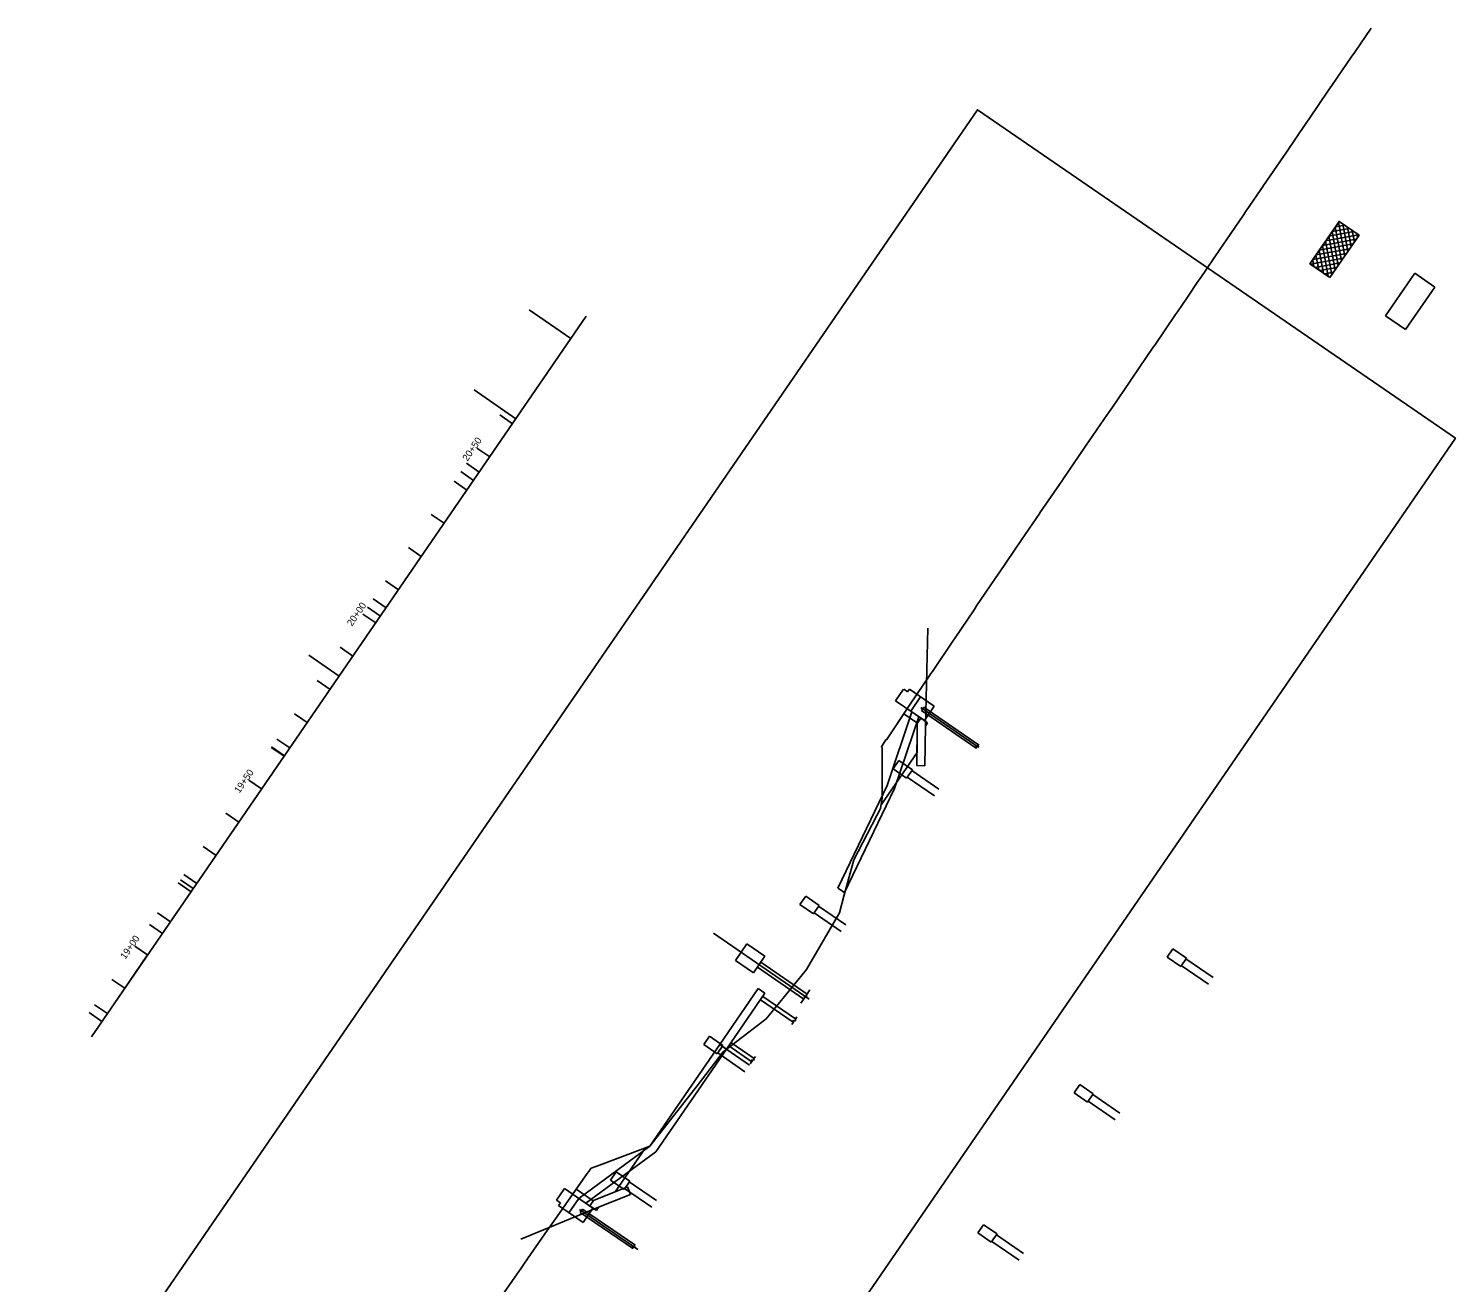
# Model space of a CAD drawing. Extents: x 2379438 to 2380801, y 331550 to 333566.
# Drawn here: x 2379858.6 to 2380212.9, y 332401.2 to 332712.4 of the extents above; entities that cross this region are included whole.
import ezdxf

# ---------------------------------------------------------------- set-up
doc = ezdxf.new("R2010")
doc.units = 0
for name, color, linetype in [('Auto Dimensioning', 7, 'Continuous'), ('Dimension Lines', 7, 'Continuous'), ('Dimension_Lines', 7, 'Continuous'), ('E_SMU_Mis_Existing_Ground_Lines', 7, 'Continuous'), ('E_SMU_Piles_concrete', 7, 'Continuous'), ('Old_Level_10', 7, 'Continuous'), ('P_SMU_Catwalk', 7, 'Continuous'), ('P_SMU_Pipe_Piles', 7, 'Continuous'), ('P_SMU_Steel_Pile', 7, 'Continuous'), ('P_SMU_SupportLines', 7, 'Continuous'), ('P_SMU_Timber', 7, 'Continuous'), ('P_SMU_Workline', 7, 'Continuous'), ('Rip Rap', 7, 'Continuous'), ('Scratch_Level_1', 7, 'Continuous'), ('Scratch_Level_8', 7, 'Continuous'), ('Sheet Data Text CELL', 7, 'Continuous')]:
    doc.layers.add(name, color=color, linetype=linetype)

msp = doc.modelspace()

# ---------------------------------------------------------------- linework, layer by layer
at = {"layer": 'Auto Dimensioning'}
for p, q in [((2379874.24, 332462.14), (2379997.1, 332640.97)), ((2379993.3, 332635.44), (2379982.91, 332642.58)), ((2379979.64, 332615.56), (2379969.25, 332622.69)), ((2379969.11, 332600.23), (2379965.92, 332602.43)), ((2379970.53, 332602.29), (2379967.34, 332604.49)), ((2379947.4, 332568.63), (2379944.2, 332570.82)), ((2379945.98, 332566.56), (2379942.79, 332568.76)), ((2379935.76, 332551.68), (2379928.21, 332556.86)), ((2379922.09, 332531.78), (2379918.89, 332533.98)), ((2379923.5, 332533.85), (2379920.31, 332536.04)), ((2379900.38, 332500.2), (2379897.19, 332502.39)), ((2379898.97, 332498.14), (2379895.78, 332500.33)), ((2379891.87, 332487.8), (2379888.68, 332490)), ((2379878.2, 332467.91), (2379875.01, 332470.1))]:
    msp.add_line(p, q, dxfattribs=at)
for points in [[(2379977.32, 332267.82), (2380212.89, 332610.7), (2380094.2, 332692.24), (2379858.63, 332349.37)], [(2379858.63, 332349.37), (2379977.32, 332267.82), (2380212.89, 332610.7), (2380094.2, 332692.24)]]:
    msp.add_lwpolyline(points, close=True, dxfattribs=at)
at = {"layer": 'Dimension Lines'}
for p, q in [((2380036.96, 332485.18), (2380034.13, 332481.06)), ((2380041.41, 332482.12), (2380036.96, 332485.18)), ((2380038.58, 332478), (2380034.13, 332481.06)), ((2380041.41, 332482.12), (2380038.58, 332478))]:
    msp.add_line(p, q, dxfattribs=at)
at = {"layer": 'Dimension_Lines'}
for points in [[(2380093.82, 332533.7), (2380094.02, 332534), (2380093.87, 332534.28), (2380094.49, 332534.19), (2380094.34, 332534.46), (2380094.54, 332534.76)], [(2380050.4, 332470.51), (2380051.36, 332471.91), (2380051.21, 332472.19), (2380051.83, 332472.1), (2380051.68, 332472.37), (2380052.64, 332473.78)], [(2380048.12, 332465.22), (2380048.6, 332465.92), (2380048.45, 332466.2), (2380049.07, 332466.11), (2380048.92, 332466.39), (2380049.4, 332467.09)], [(2380037.82, 332455.43), (2380038.3, 332456.13), (2380038.15, 332456.4), (2380038.78, 332456.32), (2380038.62, 332456.59), (2380039.1, 332457.29)], [(2380008.5, 332409.52), (2380008.71, 332409.82), (2380008.55, 332410.1), (2380009.18, 332410.01), (2380009.02, 332410.28), (2380009.23, 332410.58)]]:
    msp.add_lwpolyline(points, dxfattribs=at)
at = {"layer": 'E_SMU_Mis_Existing_Ground_Lines'}
msp.add_lwpolyline([(2379976.13, 332397.88), (2379981.09, 332404.98), (2379981.77, 332405.97), (2379986.83, 332413.2), (2379987.4, 332414.04), (2379989.85, 332417.54), (2379991.93, 332420.52), (2379997.34, 332428.17), (2379997.72, 332428.7), (2379998.26, 332429.47), (2379998.32, 332429.56), (2379999.69, 332430), (2380001.33, 332430.62), (2380012.92, 332434.97), (2380024.59, 332450.01), (2380031.1, 332458.45), (2380034.3, 332460.91), (2380037.44, 332463.32), (2380041.76, 332466.58), (2380049.62, 332476.22), (2380051.77, 332478.85), (2380058.23, 332489.95), (2380059.97, 332492.93), (2380061.06, 332497.05), (2380063.55, 332506.03), (2380066.86, 332512.45), (2380069.23, 332517.05), (2380070.12, 332518.78), (2380070.59, 332521.34), (2380070.56, 332533.58), (2380070.61, 332533.71), (2380070.41, 332533.99), (2380070.47, 332534.3), (2380071.46, 332535.84), (2380071.61, 332535.89), (2380071.81, 332536.06), (2380076.87, 332543.67), (2380077.37, 332544.46), (2380082.42, 332551.93), (2380082.67, 332552.3), (2380083.04, 332552.85), (2380088.29, 332560.62), (2380088.53, 332560.96), (2380093.38, 332568.14), (2380093.91, 332568.93), (2380094.02, 332569.09), (2380099.53, 332577.22), (2380099.58, 332577.28), (2380103.25, 332582.7), (2380105.15, 332585.49), (2380105.16, 332585.5), (2380109.69, 332592.13), (2380109.74, 332592.2), (2380115.29, 332600.31), (2380115.4, 332600.47), (2380120.89, 332608.49), (2380121.06, 332608.73), (2380126.49, 332616.67), (2380126.72, 332617), (2380127.71, 332618.45), (2380132.11, 332624.87), (2380132.37, 332625.26), (2380132.59, 332625.58), (2380137.87, 332633.33), (2380138.23, 332633.85), (2380143.41, 332641.46), (2380143.86, 332642.12), (2380146.34, 332645.76), (2380148.97, 332649.62), (2380149.5, 332650.39), (2380154.56, 332657.8), (2380155.14, 332658.65), (2380160.15, 332665.98), (2380160.79, 332666.91), (2380164.58, 332672.48), (2380164.98, 332673.06), (2380165.25, 332673.46), (2380170.17, 332680.65), (2380170.91, 332681.73), (2380175.78, 332688.86), (2380176.56, 332689.99), (2380181.4, 332697.07), (2380182.22, 332698.26), (2380183.64, 332700.35), (2380187.03, 332705.3), (2380187.87, 332706.51), (2380191.96, 332712.45)], dxfattribs=at)
at = {"layer": 'E_SMU_Piles_concrete'}
for p, q in [((2380076.77, 332526.57), (2380083.52, 332521.94)), ((2380077.9, 332528.22), (2380084.65, 332523.58)), ((2380053.64, 332492.9), (2380060.38, 332488.27)), ((2380054.77, 332494.55), (2380061.52, 332489.91)), ((2380145.96, 332481.46), (2380152.71, 332476.82)), ((2380144.83, 332479.81), (2380151.58, 332475.18)), ((2380030.88, 332459.77), (2380037.62, 332455.13)), ((2380029.74, 332458.12), (2380036.49, 332453.48)), ((2380121.7, 332446.14), (2380128.44, 332441.51)), ((2380122.83, 332447.79), (2380129.58, 332443.15)), ((2380006.63, 332424.48), (2380013.37, 332419.84)), ((2380007.76, 332426.12), (2380014.51, 332421.49)), ((2380097.8, 332411.36), (2380104.55, 332406.73)), ((2380098.93, 332413.01), (2380105.68, 332408.37))]:
    msp.add_line(p, q, dxfattribs=at)
at = {"layer": 'Old_Level_10'}
for p, q in [((2380188.84, 332661.21), (2380180.66, 332659.69)), ((2380187.68, 332662.01), (2380181.45, 332660.85)), ((2380183.8, 332653.58), (2380182.24, 332661.99)), ((2380186.51, 332662.8), (2380182.25, 332662.01)), ((2380184.6, 332654.74), (2380183.04, 332663.16)), ((2380185.35, 332663.6), (2380183.05, 332663.18)), ((2380185.4, 332655.9), (2380183.84, 332664.32)), ((2380184.19, 332664.4), (2380183.85, 332664.34)), ((2380186.2, 332657.07), (2380184.93, 332663.89)), ((2380187, 332658.23), (2380186.1, 332663.09)), ((2380187.8, 332659.39), (2380187.26, 332662.29)), ((2380188.6, 332660.55), (2380188.42, 332661.49)), ((2380186.68, 332657.76), (2380178.26, 332656.2)), ((2380187.48, 332658.92), (2380179.06, 332657.36)), ((2380181.25, 332650.92), (2380179.84, 332658.51)), ((2380188.27, 332660.09), (2380179.86, 332658.53)), ((2380182.2, 332651.25), (2380180.64, 332659.67)), ((2380183, 332652.41), (2380181.44, 332660.83)), ((2380185.08, 332655.44), (2380176.89, 332653.92)), ((2380177.76, 332653.32), (2380177.45, 332655.02)), ((2380185.88, 332656.6), (2380177.46, 332655.04)), ((2380184.28, 332654.27), (2380178.05, 332653.12)), ((2380178.93, 332652.52), (2380178.25, 332656.18)), ((2380180.09, 332651.72), (2380179.04, 332657.34)), ((2380183.48, 332653.11), (2380179.22, 332652.32)), ((2380182.68, 332651.95), (2380180.38, 332651.52)), ((2380181.88, 332650.78), (2380181.54, 332650.72)), ((2380202.77, 332651.64), (2380195.53, 332641.11)), ((2380207.75, 332648.21), (2380202.77, 332651.64)), ((2380200.52, 332637.68), (2380207.75, 332648.21)), ((2380195.53, 332641.11), (2380200.52, 332637.68)), ((2380070.29, 332519.71), (2380079.21, 332532.68)), ((2380011.79, 332434.55), (2380004.31, 332423.67))]:
    msp.add_line(p, q, dxfattribs=at)
msp.add_lwpolyline([(2380181.74, 332650.58), (2380188.98, 332661.11), (2380183.99, 332664.54), (2380176.75, 332654.01), (2380181.74, 332650.58)], dxfattribs=at)
for points in [[(2380079.29, 332539.89), (2380079.35, 332539.97), (2380075.96, 332542.3), (2380071.81, 332536.06), (2380071.61, 332535.89), (2380071.46, 332535.84), (2380070.47, 332534.3), (2380070.41, 332533.99), (2380070.61, 332533.71), (2380070.56, 332533.58), (2380070.59, 332521.34), (2380070.29, 332519.71), (2380079.21, 332532.68)], [(2379994.61, 332424.3), (2379997.34, 332428.17), (2379997.72, 332428.7), (2379998.26, 332429.47), (2379998.32, 332429.56), (2379999.69, 332430), (2380011.79, 332434.55), (2380004.31, 332423.67), (2379998.86, 332421.5), (2379998.8, 332421.42)]]:
    msp.add_lwpolyline(points, close=True, dxfattribs=at)
at = {"layer": 'P_SMU_Catwalk'}
for p, q in [((2380030.24, 332460.19), (2380039.81, 332474.12)), ((2380041.46, 332472.99), (2380039.81, 332474.12)), ((2380031.89, 332459.06), (2380041.46, 332472.99)), ((2380048.48, 332465.74), (2380040.33, 332471.34)), ((2380049.05, 332466.57), (2380040.9, 332472.16)), ((2380031.89, 332459.06), (2380030.24, 332460.19)), ((2380038.18, 332455.95), (2380032.46, 332459.88)), ((2380038.75, 332456.77), (2380033.02, 332460.7))]:
    msp.add_line(p, q, dxfattribs=at)
at = {"layer": 'P_SMU_Pipe_Piles'}
for p, q in [((2380040.42, 332480.68), (2380051.95, 332472.76)), ((2380051.1, 332471.52), (2380039.57, 332479.44))]:
    msp.add_line(p, q, dxfattribs=at)
at = {"layer": 'P_SMU_Steel_Pile'}
for p, q in [((2380080.32, 332543.15), (2380080.89, 332543.97)), ((2380080.32, 332543.15), (2380093.9, 332533.82)), ((2380080.89, 332543.97), (2380094.46, 332534.65)), ((2379996.18, 332419.37), (2379995.61, 332418.55)), ((2379995.61, 332418.55), (2380008.58, 332409.64)), ((2379996.18, 332419.37), (2380009.15, 332410.47))]:
    msp.add_line(p, q, dxfattribs=at)
at = {"layer": 'P_SMU_SupportLines'}
for p, q in [((2380080.12, 332543.89), (2380094.6, 332533.95)), ((2380028.68, 332487.84), (2380052.47, 332471.49)), ((2379995.4, 332419.31), (2380009.92, 332409.33))]:
    msp.add_line(p, q, dxfattribs=at)
at = {"layer": 'P_SMU_Timber'}
for p, q in [((2380059.57, 332499.07), (2380061.24, 332497.93)), ((2380012.92, 332434.97), (2380030.24, 332460.19)), ((2380014.37, 332433.56), (2380031.89, 332459.06)), ((2379995.26, 332422.03), (2380012.92, 332434.97)), ((2379997.01, 332420.83), (2380014.37, 332433.56))]:
    msp.add_line(p, q, dxfattribs=at)
for points in [[(2380059.57, 332499.07), (2380071.8, 332524.52), (2380077.92, 332542.77)], [(2380079.64, 332541.6), (2380073.66, 332523.77), (2380061.24, 332497.93)]]:
    msp.add_lwpolyline(points, dxfattribs=at)
at = {"layer": 'P_SMU_Workline'}
for p, q in [((2380081.28, 332539.25), (2380081.89, 332563.58)), ((2380000.16, 332419.87), (2379980.82, 332411.92))]:
    msp.add_line(p, q, dxfattribs=at)
at = {"layer": 'Rip Rap'}
for p, q in [((2380073.29, 332528.66), (2380074.71, 332530.72)), ((2380078.05, 332528.42), (2380074.71, 332530.72)), ((2380076.63, 332526.36), (2380073.29, 332528.66)), ((2380076.63, 332526.36), (2380078.05, 332528.42)), ((2380050.16, 332494.99), (2380051.57, 332497.05)), ((2380053.5, 332492.69), (2380050.16, 332494.99)), ((2380054.91, 332494.75), (2380051.57, 332497.05)), ((2380053.5, 332492.69), (2380054.91, 332494.75)), ((2380141.35, 332481.9), (2380142.76, 332483.96)), ((2380144.69, 332479.6), (2380141.35, 332481.9)), ((2380146.1, 332481.66), (2380142.76, 332483.96)), ((2380144.69, 332479.6), (2380146.1, 332481.66)), ((2380026.26, 332460.21), (2380027.68, 332462.27)), ((2380029.6, 332457.91), (2380026.26, 332460.21)), ((2380031.02, 332459.97), (2380027.68, 332462.27)), ((2380029.6, 332457.91), (2380031.02, 332459.97)), ((2380118.22, 332448.23), (2380119.63, 332450.29)), ((2380122.97, 332448), (2380119.63, 332450.29)), ((2380121.56, 332445.93), (2380118.22, 332448.23)), ((2380121.56, 332445.93), (2380122.97, 332448)), ((2380003.15, 332426.56), (2380004.56, 332428.63)), ((2380007.9, 332426.33), (2380004.56, 332428.63)), ((2380006.49, 332424.27), (2380003.15, 332426.56)), ((2380006.49, 332424.27), (2380007.9, 332426.33)), ((2380094.32, 332413.45), (2380095.74, 332415.51)), ((2380097.66, 332411.15), (2380094.32, 332413.45)), ((2380099.08, 332413.21), (2380095.74, 332415.51)), ((2380097.66, 332411.15), (2380099.08, 332413.21))]:
    msp.add_line(p, q, dxfattribs=at)
at = {"layer": 'Scratch_Level_1'}
for p, q in [((2379978.79, 332614.32), (2379975.6, 332616.51)), ((2379973.13, 332606.08), (2379969.94, 332608.27)), ((2379967.47, 332597.84), (2379964.27, 332600.03)), ((2379961.8, 332589.59), (2379958.61, 332591.79)), ((2379956.14, 332581.35), (2379952.95, 332583.55)), ((2379950.48, 332573.11), (2379947.29, 332575.3)), ((2379944.82, 332564.87), (2379941.62, 332567.06)), ((2379939.15, 332556.63), (2379935.96, 332558.82)), ((2379933.49, 332548.38), (2379930.3, 332550.58)), ((2379927.83, 332540.14), (2379924.63, 332542.34)), ((2379922.16, 332531.9), (2379918.97, 332534.09)), ((2379916.5, 332523.66), (2379913.31, 332525.85)), ((2379910.84, 332515.41), (2379907.65, 332517.61)), ((2379905.18, 332507.17), (2379901.98, 332509.37)), ((2379899.51, 332498.93), (2379896.32, 332501.12)), ((2379893.85, 332490.69), (2379890.66, 332492.88)), ((2379888.19, 332482.45), (2379885, 332484.64)), ((2379888.19, 332482.45), (2379883.27, 332475.29)), ((2379882.53, 332474.2), (2379879.33, 332476.4)), ((2379876.86, 332465.96), (2379873.67, 332468.16))]:
    msp.add_line(p, q, dxfattribs=at)
at = {"layer": 'Scratch_Level_8'}
for p, q in [((2380075.89, 332548.41), (2380073.91, 332545.53)), ((2380076.86, 332547.75), (2380075.9, 332548.41)), ((2380077.33, 332548.44), (2380076.86, 332547.75)), ((2380083.48, 332544.21), (2380077.33, 332548.44)), ((2380081.03, 332540.64), (2380073.91, 332545.53)), ((2380077.65, 332542.96), (2380080.1, 332546.54)), ((2380083.48, 332544.21), (2380081.03, 332540.64)), ((2379989.73, 332421.58), (2379991.71, 332424.47)), ((2379998.77, 332419.62), (2379991.71, 332424.47)), ((2379990.69, 332420.92), (2379989.73, 332421.58)), ((2379990.22, 332420.24), (2379990.69, 332420.92)), ((2379992.81, 332418.46), (2379995.26, 332422.03)), ((2379996.32, 332416.04), (2379990.22, 332420.24)), ((2379998.77, 332419.62), (2379996.32, 332416.04))]:
    msp.add_line(p, q, dxfattribs=at)
at = {"layer": 'Sheet Data Text CELL'}
for p, q in [((2380080.2, 332541.21), (2380079.29, 332539.89)), ((2380081.85, 332540.08), (2380080.2, 332541.21)), ((2380079.29, 332539.89), (2380079.17, 332529.44)), ((2380081.17, 332529.41), (2380081.28, 332539.25)), ((2380081.28, 332539.25), (2380081.85, 332540.08)), ((2380079.17, 332529.44), (2380081.17, 332529.41)), ((2380007.33, 332424.87), (2379998.86, 332421.5)), ((2380008.07, 332423.01), (2380007.33, 332424.87)), ((2379998.86, 332421.5), (2379997.95, 332420.18)), ((2380000.16, 332419.87), (2380008.07, 332423.01)), ((2379997.95, 332420.18), (2379999.6, 332419.05)), ((2379999.6, 332419.05), (2380000.16, 332419.87))]:
    msp.add_line(p, q, dxfattribs=at)

# ---------------------------------------------------------------- texts
at = {"layer": 'Auto Dimensioning'}
for s, p in [('20+50', (2379967.61, 332604.88)), ('20+00', (2379938.94, 332563.91)), ('19+50', (2379910.98, 332522.46)), ('19+00', (2379882.66, 332481.25))]:
    msp.add_text(s, height=1.717, rotation=55.5093, dxfattribs=at).set_placement(p)

doc.saveas('drawing.dxf')
